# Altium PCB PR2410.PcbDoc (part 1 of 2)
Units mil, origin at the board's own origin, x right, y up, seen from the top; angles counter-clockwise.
Board outline 2750 x 3900 mil, 2 copper layers (Top Layer, Bottom Layer), stack 61.6 mil thick; 140 components, 78 nets, 324 pads, 132 vias.
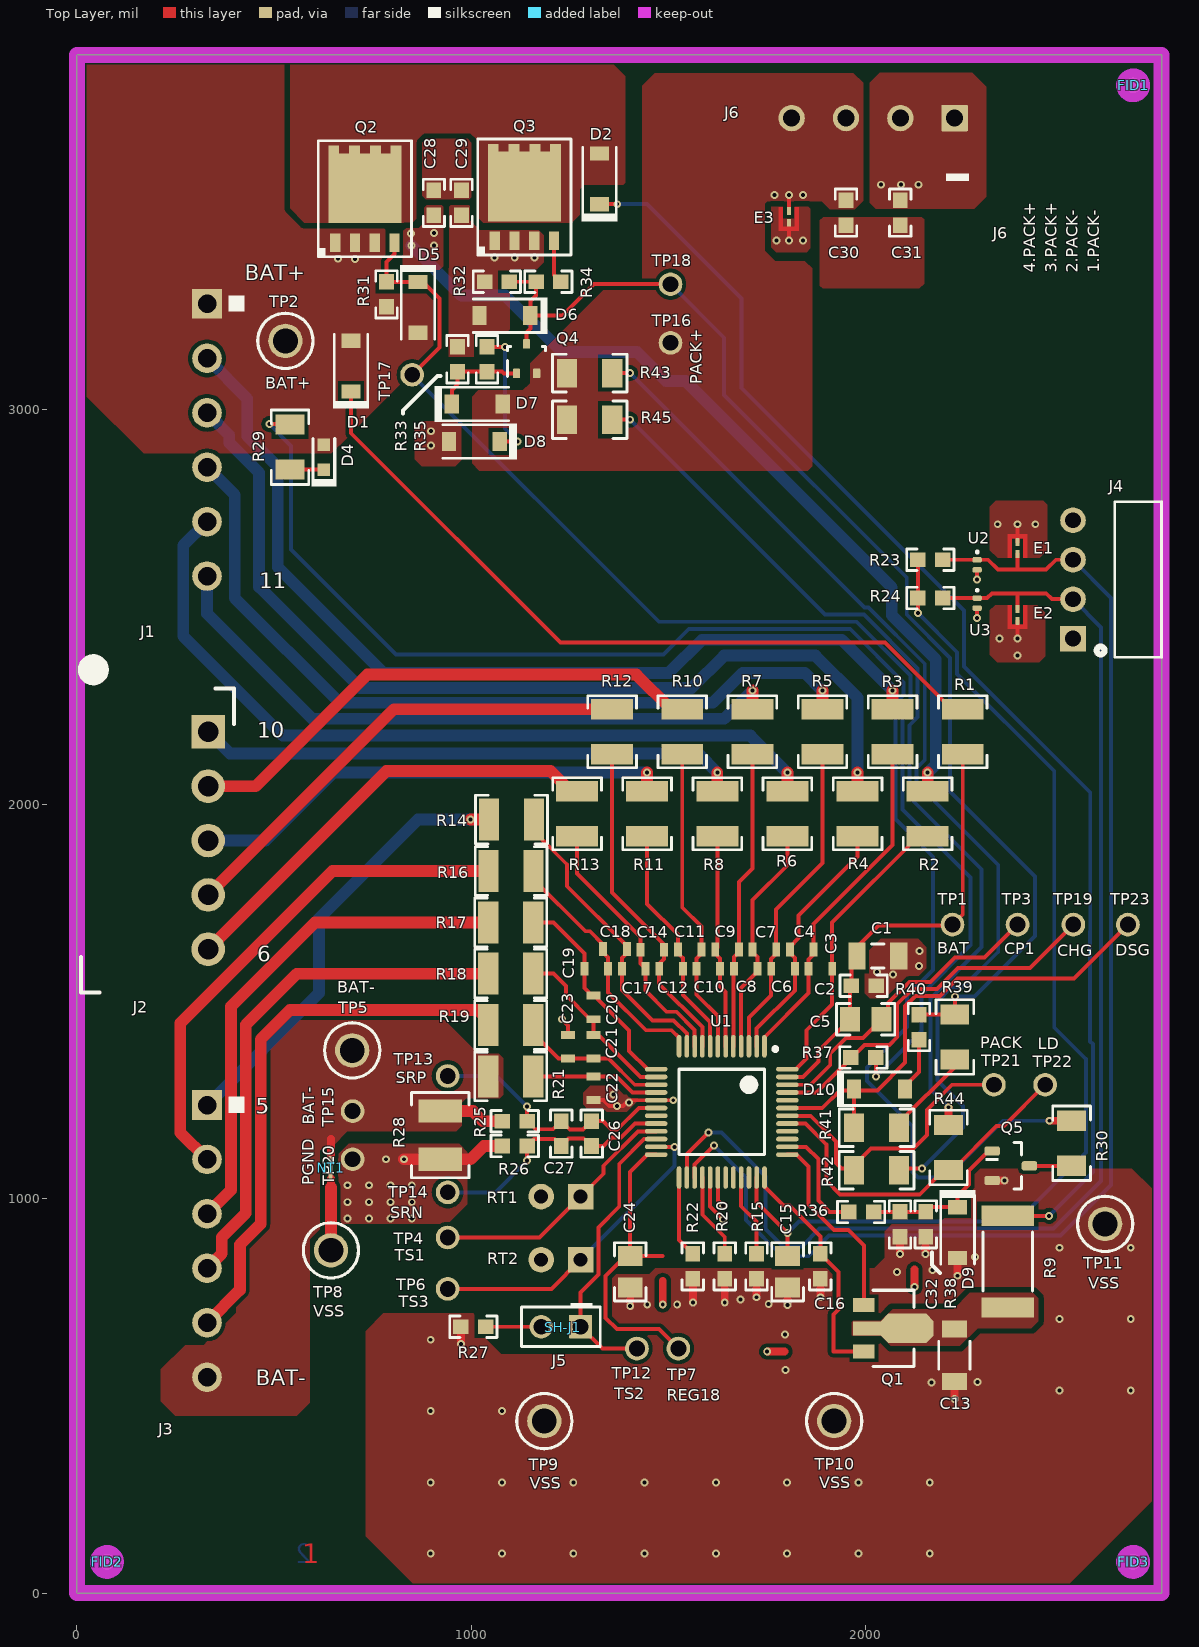
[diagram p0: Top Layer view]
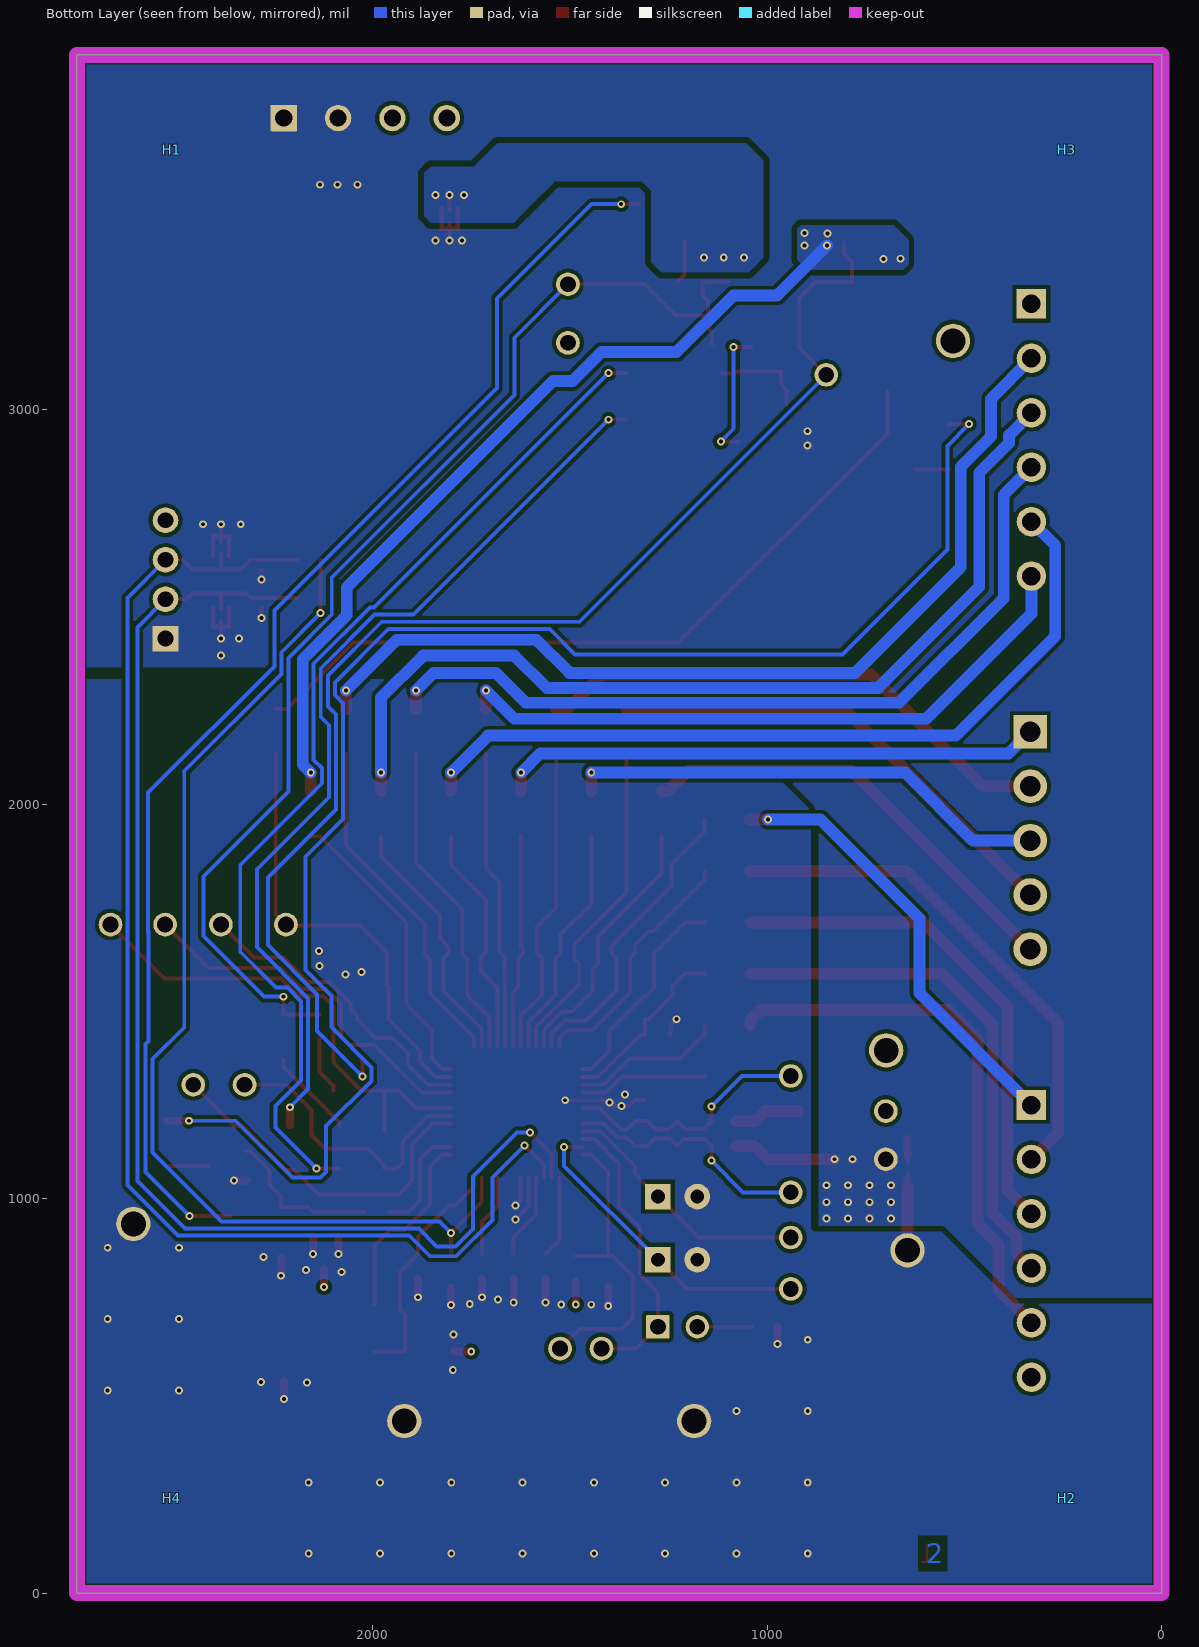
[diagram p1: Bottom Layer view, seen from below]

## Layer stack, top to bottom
Top Solder: solder mask 0.4, Solder Resist, Dk 3.5
Top Layer: signal copper 2.8
Dielectric: prepreg 56, FR-4 High Tg, Dk 4.2
Bottom Layer: signal copper 2.8
Bottom Solder: solder mask 0.4, Solder Resist, Dk 3.5

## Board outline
0,0 2750,0 2750,3900 0,3900

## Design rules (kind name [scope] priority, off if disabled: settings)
AcuteAngle [All] p1: minimum=4.50000000000000E+0001 checktracksonly=FALSE
AssemblyTestPointUsage [All] p1: valid=2
BoardOutlineClearance BoardOutlineClearance_MountingHoles [OnCopper and InComponentClass('Mounting Holes')] p1: gap=39.37 ignorepadtopadclearanceinfootprint=FALSE
BoardOutlineClearance BoardOutlineClearance_Poly [OnCopper and IsPoly] p2: gap=20 ignorepadtopadclearanceinfootprint=FALSE
BoardOutlineClearance [OnCopper and Not InComponentClass('Logo') and not InComponentClass('FiducialMark') and not InRegion(1000,500,4000,800) and not InPoly] p3: gap=18 ignorepadtopadclearanceinfootprint=FALSE
Clearance Clearance_FiducialMark [IsKeepOut and InComponentClass('FiducialMark') vs IsPad and InComponentClass('FiducialMark')] p1: gap=0 ignorepadtopadclearanceinfootprint=FALSE
Clearance Clearance_Iskeepot [IsKeepOut] p2: gap=5 ignorepadtopadclearanceinfootprint=FALSE
Clearance Clearance_NPTH [IsThruPin And (PadIsPlated = 'False')] p3: gap=20 ignorepadtopadclearanceinfootprint=FALSE
Clearance Clearance_Poly-poly [InPolygon vs InPolygon] p4: gap=15 ignorepadtopadclearanceinfootprint=FALSE
Clearance Clearance_Polygon [InPolygon] p5: gap=10 ignorepadtopadclearanceinfootprint=FALSE
Clearance [All] p6: gap=7.87 ignorepadtopadclearanceinfootprint=FALSE
ComponentClearance ComponentClearance_shunt [HasFootprint('CONN_PEC02SAAN') vs HasFootprint('SNT-100-BK-G')] p1: gap=0 collisioncheckmode=3 verticalgap=0 showdistances=FALSE
ComponentClearance ComponentClearance_Screw-Nut [(HasFootprint('Keystone_1902C')) vs (HasFootprint('NY PMS 440 0025 PH'))] p2: gap=5 collisioncheckmode=3 verticalgap=10 showdistances=FALSE
ComponentClearance [All] p3: gap=10 collisioncheckmode=3 verticalgap=10 showdistances=FALSE
DiffPairsRouting [All] p1: maxlimit=100 minlimit=10 mostfreqgap=10 toplayer_minwidth=15 toplayer_maxwidth=15 toplayer_prefwidth=15 bottomlayer_minwidth=15 bottomlayer_maxwidth=15 bottomlayer_prefwidth=15 maxuncoupledlength=1000
FabricationTestPointUsage TestPointUsage [All] p1: valid=2 allowmultiple=FALSE
FabricationTestpoint Testpoint [All] p1: side=3 testpointundercomponent=TRUE minsize=40 maxsize=100 preferedsize=60 minholesize=0 maxholesize=40 preferedholesize=32 testpointgrid=1 allowsidetop=TRUE allowsidebottom=TRUE usegrid=TRUE gridtolerance=0.01
FanoutControl Fanout_LCC [IsLCC] p1: bgadir=Out bgaviamode=Centered fanoutstyle=Auto fanoutdirection=Alternating viagrid=1 // Fanout_LCC (Default Rule)
FanoutControl Fanout_BGA [IsBGA] p2: bgadir=Out bgaviamode=Centered fanoutstyle=Auto fanoutdirection=Alternating viagrid=1 // Fanout_BGA (Default Rule)
FanoutControl Fanout_Default [All] p4: bgadir=Out bgaviamode=Centered fanoutstyle=Auto fanoutdirection=Alternating viagrid=1 // Fanout_Default (Default Rule)
FanoutControl Fanout_Small [(CompPinCount < 5)] p5: bgadir=Out bgaviamode=Centered fanoutstyle=Auto fanoutdirection=OutThenIn viagrid=1 // Fanout_Small (Default Rule)
HoleSize [All] p1: absolutevalues=TRUE maxlimit=251 minlimit=7.87 maxpercent=80.000 minpercent=20.000
HoleToHoleClearance [All] p1: gap=12 allowstackedmicrovias=TRUE
MinimumAnnularRing MinimumAnnularRing_ThermalPadVias [IsVia] p1: minimumring=5
MinimumAnnularRing [All] p2: minimumring=7.5
MinimumSolderMaskSliver MinimumSolderMaskSliver_Logo [InComponentClass('Logo') vs InComponentClass('Logo')] p1: minsoldermaskwidth=0.7
MinimumSolderMaskSliver [All] p2: minsoldermaskwidth=3.9
PlaneConnect [All] p1: planeconnectstyle=Relief reliefexpansion=10 reliefentries=4 reliefconductorwidth=10 reliefairgap=10
PolygonConnect [All] p1: connectstyle=Direct reliefconductorwidth=10 reliefentries=4 polygonreliefangle="90 Angle" airgapwidth=10
RoutingVias ThermalPadVias [IsVia and InAnyComponent] p1: holewidth=7.87 width=19.68 viastyle="Through Hole" minholewidth=7.87 minwidth=19.68 maxholewidth=12.99 maxwidth=23.62
RoutingVias [All] p2: holewidth=16 width=34 viastyle="Through Hole" minholewidth=7.87 minwidth=20 maxholewidth=40 maxwidth=65
SilkToBoardRegionClearance [Not ((IsComment or IsDesignator) And (Hide <> 'False')) and not InRegion(1000,500,4000,800)] p1:
SilkToSilkClearance SilkToSilkClearance_Pb-FreeLogo [(HasFootprint('Pb-Free_Overlay_Medium') OR HasFootprint('Pb-Free_Overlay_Small')) vs (HasFootprint('Pb-Free_Overlay_Medium') OR HasFootprint('Pb-Free_Overlay_Small'))] p1: silktosilkclearance=0
SilkToSilkClearance [All] p2: silktosilkclearance=4
SilkToSolderMaskClearance SilkToComponentPadClearance [(IsPad or IsFill or IsRegion) and InAnycomponent] p1: minsilkscreentomaskgap=5 clearancetoexposedcopper=TRUE
SilkToSolderMaskClearance "Silk to Solder Mask Opening" [All] p2: minsilkscreentomaskgap=3.94 clearancetoexposedcopper=FALSE
SolderMaskExpansion SolderMaskExpansion_NPTH [IsThruPin And (PadIsPlated = 'False')] p1: expansion=5
SolderMaskExpansion SolderMaskExpansion_PTH [IsThruPin] p2: expansion=2.5
SolderMaskExpansion [All] p3: expansion=0
UnRoutedNet [All] p1: checkbadconnections=TRUE
Width [All] p1: maxlimit=100 minlimit=6 preferedwidth=10 checkconnectedcopper=TRUE
13 further rules are at their usual default settings.

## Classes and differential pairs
component class Shunt: SH-J1
component class Header: J5
component class PR2410_Monitor: C1 C2 C3 C4 C5 C6 C7 C8 C9 C10 C11 C12 C13 C14 C15 C16 C17 C18 C19 C20 C21 C22 C23 C24 C26 C27 D1 D2 E1 E2 J1 J2 J3 J4 J5 NT1 Q1 R1 R2 R3 R4 R5 R6 R7 R8 R9 R10 R11 R12 R13 R14 R15 R16 R17 R18 R19 R20 R21 R22 R23 R24 R25 R26 R27 R28 RT1 RT2 TP1 TP2 TP3 TP4 TP5 TP6 TP7 TP8 TP9 TP10 TP11 TP12 TP13 TP14 TP15 U1 U2 U3
component class PR2410_FETs: C28 C29 C30 C31 C32 D4 D5 D6 D7 D8 D9 D10 E3 J6 Q2 Q3 Q4 Q5 R29 R30 R31 R32 R33 R34 R35 R36 R37 R38 R39 R40 R41 R42 R43 R44 R45 TP16 TP17 TP18 TP19 TP20 TP21 TP22 TP23
component class PR2410_Hardware: FID1 FID2 FID3 H1 H2 H3 H4 SH-J1 ZZ1 ZZ2 ZZ3 ZZ4
component class FiducialMark: FID1 FID2 FID3
component class AssemblyNote: ZZ1 ZZ2 ZZ3 ZZ4

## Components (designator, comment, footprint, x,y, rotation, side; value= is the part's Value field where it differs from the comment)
C1 "C3216X7R2A105K160AA" 1206_180L 2030.61,1615 r0 top value=1uF
C2 "GCM1885C2A101JA16D" 0603 1994.88,1540 r0 top value=100pF
C3 "C1608X7R1H224K080AB" 0603S 1885,1583.08 r180 top value=0.22uF
C4 "C1608X7R1H224K080AB" 0603S 1837.67,1632.08 r180 top value=0.22uF
C5 "GCM219R71E474KA55D" 0805_HV 1999.88,1455 r0 top value=0.47uF
C6 "C1608X7R1H224K080AB" 0603S 1790.33,1583.08 r180 top value=0.22uF
C7 "C1608X7R1H224K080AB" 0603S 1743,1632.08 r180 top value=0.22uF
C8 "C1608X7R1H224K080AB" 0603S 1695.67,1583.08 r180 top value=0.22uF
C9 "C1608X7R1H224K080AB" 0603S 1648.33,1632.08 r180 top value=0.22uF
C10 "C1608X7R1H224K080AB" 0603S 1601,1583.08 r180 top value=0.22uF
C11 "C1608X7R1H224K080AB" 0603S 1553.67,1632.08 r180 top value=0.22uF
C12 "C1608X7R1H224K080AB" 0603S 1506.33,1583.08 r180 top value=0.22uF
C13 "C3216X7R2A105K160AA" 1206_180 2225,603 r270 top value=1uF
C14 "C1608X7R1H224K080AB" 0603S 1459,1631.08 r180 top value=0.22uF
C15 "EMK212B7105KG-T" 0805_HV 1801.91,814.49 r90 top value=1uF
C16 "C0603C223K4RACTU" 0603 1885,828.5 r90 top value=0.022uF
C17 "C1608X7R1H224K080AB" 0603S 1411.67,1583.08 r180 top value=0.22uF
C18 "C1608X7R1H224K080AB" 0603S 1364.33,1633.08 r180 top value=0.22uF
C19 "C1608X7R1H224K080AB" 0603S 1317,1583.08 r180 top value=0.22uF
C20 "C1608X7R1H224K080AB" 0603S 1310,1485 r270 top value=0.22uF
C21 "C1608X7R1H224K080AB" 0603S 1310,1385 r270 top value=0.22uF
C22 "C1608X7R1H224K080AB" 0603S 1310,1280 r270 top value=0.22uF
C23 "C1608X7R1H224K080AB" 0603S 1245,1385 r90 top value=0.22uF
C24 "EMK212B7225KG-T" 0805_HV 1402.8,814.49 r90 top value=2.2uF
C26 "GCM1885C2A101JA16D" 0603 1305,1165 r270 top value=100pF
C27 "885012206095" 0603 1228,1165 r270 top value=0.1uF
C28 "GCJ188R72A104KA01D" 0603 905,3525 r270 top value=0.1uF
C29 "GCJ188R72A104KA01D" 0603 975,3525 r90 top value=0.1uF
C30 "GCJ188R72A104KA01D" 0603 1950,3500 r90 top value=0.1uF
C31 "GCJ188R72A104KA01D" 0603 2087.8,3500 r270 top value=0.1uF
C32 "885012206095" 0603 2087,934.72 r90 top value=0.1uF
D1 "BAT46W-7-F" SOD-123 695,3111 r90 top value=100V
D2 "BAT46W-7-F" SOD-123 1325,3586.02 r90 top value=100V
D4 "150060RS75000" WL-SMCW_RED 626,2880 r90 top value=Red
D5 "MMSZ5246B-7-F" SOD-123 865,3260 r270 top value=16V
D6 "MMSZ5246B-7-F" SOD-123 1085,3238.98 r180 top value=16V
D7 "MMSZ5246B-7-F" SOD-123 1015,3015 r0 top value=16V
D8 "1N4148W-7-F" SOD-123 1007.73,2920 r180 top value=100V
D9 "MMSZ4697T1G" SOD-123 2233,914 r270 top value=10V
D10 "BAT46W-7-F" SOD-123 2035,1278.57 r0 top value=100V
E1 "Spark Gap" SPARK_GAP2 2385,2655 r180 top
E2 "Spark Gap" SPARK_GAP2 2385,2475 r0 top
E3 "Spark Gap" SPARK_GAP2 1805,3484.45 r0 top
FID1 "Fiducial" Fiducial10-20 2678,3823 r0 top
FID2 "Fiducial" Fiducial10-20 76,79 r0 top
FID3 "Fiducial" Fiducial10-20 2678,79 r0 top
H1 "SJ-5303 (CLEAR)" Bumpon_SJ5003Transparent 2510,3660 r270 bottom
H2 "SJ-5303 (CLEAR)" Bumpon_SJ5003Transparent 240,240 r180 bottom
H3 "SJ-5303 (CLEAR)" Bumpon_SJ5003Transparent 240,3660 r0 bottom
H4 "SJ-5303 (CLEAR)" Bumpon_SJ5003Transparent 2510,240 r90 bottom
J1 "395021006" HEADER_395021006 329.81,2923.64 r270 top
J2 "395021005" HEADER_395021005 195.01,1908.03 r270 top
J3 "395021006" HEADER_395021006 329.81,892.43 r270 top
J4 "22/05/3041" CONN_22-05-3041 2750,2570 r90 top
J5 "PEC02SAAN" CONN_PEC02SAAN 1227,675.28 r180 top
J6 "OSTTE040161" FP-OSTTE040161_HDR4-MFG 2018.9,3743.94 r180 top
NT1 "Net-Tie" Net-Tie_10milWide_30milLong 643,1078 r90 top net-tie
Q1 "FCX495TA" SOT-89-3 2070,671.35 r0 top value="150 V"
Q2 "BSC160N15NS5ATMA1" PG-TDSON-8 730,3535.47 r90 top value=150V
Q3 "BSC160N15NS5ATMA1" PG-TDSON-8 1134.45,3539.76 r90 top value=150V
Q4 "MOSFET_N_D3G1S2" SOT-323 1140,3130 r90 top value=60V
Q5 "PMV213SN,215" SOT-23 2367.76,1083.35 r0 top value=100V
R1 "CRCW1210100RFKEA" 1210 2246,2184.09 r90 top value=100
R2 "ERJ-14YJ200U" 1210 2157.09,1976.09 r270 top value=20
R3 "ERJ-14YJ200U" 1210 2068.18,2184.09 r270 top value=20
R4 "ERJ-14YJ200U" 1210 1979.27,1976.09 r270 top value=20
R5 "ERJ-14YJ200U" 1210 1890.36,2184.09 r270 top value=20
R6 "ERJ-14YJ200U" 1210 1801.45,1976.09 r270 top value=20
R7 "ERJ-14YJ200U" 1210 1712.55,2184.09 r270 top value=20
R8 "ERJ-14YJ200U" 1210 1623.64,1976.09 r270 top value=20
R9 "CRCW2512300RJNEG" 2512 2360,840.35 r90 top value=300
R10 "ERJ-14YJ200U" 1210 1534.73,2184.09 r270 top value=20
R11 "ERJ-14YJ200U" 1210 1445.82,1976.09 r270 top value=20
R12 "ERJ-14YJ200U" 1210 1356.91,2184.09 r270 top value=20
R13 "ERJ-14YJ200U" 1210 1268,1976.09 r270 top value=20
R14 "ERJ-14YJ200U" 1210 1101.91,1961 r0 top value=20
R15 "CRCW06031K00JNEA" 0603 1723.36,828.5 r90 top value=1.0k
R16 "ERJ-14YJ200U" 1210 1100.91,1830.8 r0 top value=20
R17 "ERJ-14YJ200U" 1210 1100,1700.6 r0 top value=20
R18 "ERJ-14YJ200U" 1210 1100,1570.4 r0 top value=20
R19 "ERJ-14YJ200U" 1210 1100,1440.2 r0 top value=20
R20 "CRCW06031K00JNEA" 0603 1642.53,828.5 r90 top value=1.0k
R21 "ERJ-14YJ200U" 1210 1100,1310 r0 top value=20
R22 "CRCW06031K00JNEA" 0603 1561.71,828.5 r90 top value=1.0k
R23 "CRCW060310K0JNEA" 0603 2163.76,2620 r0 top value=10k
R24 "CRCW060310K0JNEA" 0603 2163.76,2522.8 r0 top value=10k
R25 "Resistor" 0603 1110,1196.5 r0 top value=100
R26 "Resistor" 0603 1110,1133.5 r0 top value=100
R27 "CRCW060310K0JNEA" 0603 1005,675.28 r0 top value=10k
R28 "Resistor" 1210M 921,1161 r90 top value=0.001
R29 "CRCW12067K50JNEA" 1206 540,2905.59 r270 top value=7.5k
R30 "CRCW12067K50JNEA" 1206 2522,1140.43 r90 top value=7.5k
R31 "Resistor" 0603 785,3292.97 r90 top value=10Meg
R32 "Resistor" 0603 1065,3325 r0 top value=10Meg
R33 "Resistor" 0603 965,3128.37 r270 top value=10Meg
R34 "CRCW06030000Z0EA" 0603 1195.53,3325 r180 top value=0
R35 "Resistor" 0603 1040,3128.37 r90 top value=10k
R36 "Resistor" 0603 1988.5,966.22 r180 top value=5.1k
R37 "CRCW06035K10JNEA" 0603 1994,1358 r0 top value=5.1k
R38 "Resistor" 0603 2151.96,934.72 r90 top value=20k
R39 "CRCW12065K10JNEA" 1206 2226.02,1410 r90 top value=5.1k
R40 "CRCW06037K50FKEA" 0603 2135,1435 r90 top value=7.50k
R41 "CRCW12065K10JNEA" 1206 2027.62,1179.7 r0 top value=5.1k
R42 "CRCW12065K10JNEA" 1206 2027.62,1072 r180 top value=5.1k
R43 "CRCW12065K10JNEA" 1206 1300,3093.27 r0 top value=5.1k
R44 "CRCW12065K10JNEA" 1206 2210,1129.76 r270 top value=5.1k
R45 "CRCW12065K10JNEA" 1206 1300,2975.16 r0 top value=5.1k
RT1 "Thermistor" THERMISTOR_103AT-2 1227,1005.28 r180 top value=10k
RT2 "Thermistor" THERMISTOR_103AT-2 1227,845.28 r180 top value=10k
SH-J1 "SNT-100-BK-G" SNT-100-BK-G 1231.39,674 r180 top value=1x2
TP1 "TESTPOINT" TP_VIA_060RND040 2220,1695 r0 top
TP2 "TESTPOINT" Keystone5010 528.47,3175 r0 top
TP3 "TESTPOINT" TP_VIA_060RND040 2385,1695 r0 top
TP4 "TESTPOINT" TP_VIA_060RND040 940,901.5 r0 top
TP5 "TESTPOINT" Keystone5011 698,1376 r0 top
TP6 "TESTPOINT" TP_VIA_060RND040 940,771.18 r0 top
TP7 "TESTPOINT" TP_VIA_060RND040 1525,620 r90 top
TP8 "5006" Keystone5006 644,869 r180 top
TP9 "5006" Keystone5006 1185,436 r180 top
TP10 "5006" Keystone5006 1920,436 r180 top
TP11 "5006" Keystone5006 2607,936 r180 top
TP12 "TESTPOINT" TP_VIA_060RND040 1420,620 r90 top
TP13 "TESTPOINT" TP_VIA_060RND040 940,1311 r270 top
TP14 "TESTPOINT" TP_VIA_060RND040 940,1016 r270 top
TP15 "TESTPOINT" TP_VIA_060RND040 699,1222.02 r90 top
TP16 "TESTPOINT" TP_VIA_060RND040 1505,3170 r90 top
TP17 "TESTPOINT" TP_VIA_060RND040 850,3089 r90 top
TP18 "TESTPOINT" TP_VIA_060RND040 1505,3318.7 r90 top
TP19 "TESTPOINT" TP_VIA_060RND040 2526.5,1695 r90 top
TP20 "TESTPOINT" TP_VIA_060RND040 699,1099.98 r180 top
TP21 "TESTPOINT" TP_VIA_060RND040 2325,1288.9 r180 top
TP22 "TESTPOINT" TP_VIA_060RND040 2455,1288.9 r90 top
TP23 "TESTPOINT" TP_VIA_060RND040 2664.95,1695 r90 top
U1 "bq76952PFBR" PFB0048A_N 1635,1220 r270 top locked
U2 "TPD1E10B06DPYR" DPY0002A 2282.52,2607.21 r270 top
U3 "TPD1E10B06DPYR" DPY0002A 2282.52,2510 r270 top
ZZ1 "These assemblies are ESD sensitive, ESD precautions shall be observed." AssemblyNote -638,4601 r0 top
ZZ2 "These assemblies must be clean and free from flux and all contaminants. Use of no clean flux is not acceptable." AssemblyNote -638,4501 r0 top
ZZ3 "These assemblies must comply with workmanship standards IPC-A-610 Class 2, unless otherwise specified." AssemblyNote -638,4401 r0 top
ZZ4 "Indication provided for the D* components at their cathode side." AssemblyNote -636,4300 r0 top

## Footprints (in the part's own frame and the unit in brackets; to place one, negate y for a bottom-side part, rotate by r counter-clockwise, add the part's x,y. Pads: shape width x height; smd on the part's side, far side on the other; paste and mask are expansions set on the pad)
0603 [mm] "0603 from SM-752 data"
  rect 1x0.95 smd: 1(-0.8,0) 2(0.8,0)
  silkscreen extent -1.52,-0.69 1.52,0.69, body extent -0.87,-0.47 0.87,0.47, height 1
0603S [mil]
  rect 20x35 smd: 1(-30,0) 2(30,0)
  body extent -34,-19 34,19, height 39
0805_HV [mil] "0805 with 30mil clearance between pads"
  rect 50x63 smd: 1(-40,0) 2(40,0)
  silkscreen extent -74,-40 74,40, body extent -43,-29 43,29, height 57
1206 [mm] "1206 from SM-752 data"
  rect 1.3x1.85 smd: 1(-1.45,0) 2(1.45,0)
  silkscreen extent -2.4,-1.21 2.4,1.21, body extent -1.7,-0.9 1.7,0.9, height 1.35
1206_180 [mm] "1206_180"
  rect 1.1x1.6 smd: 1(-1.7,0) 2(1.7,0)
  silkscreen extent -0.9,-1 0.9,1, body extent -1.75,-0.95 1.75,0.95, height 1.8
1206_180L [mm] "1206_180"
  rect 1.1x1.75 smd: 1(-1.35,0) 2(1.35,0)
  silkscreen extent -0.4,-0.77 0.4,0.77, body extent -1.75,-0.95 1.75,0.95, height 1.8
1210 [mm] "1210 from SM-752 data"
  rect 1.3x2.7 smd: 1(-1.45,0) 2(1.45,0)
  silkscreen extent -2.32,-1.57 2.32,1.57, body extent -1.7,-1.35 1.7,1.35, height 1.35
1210M [mm] "1210 from SM-752 data"
  rect 1.5x2.8 smd: 1(-1.55,0) 2(1.55,0)
  silkscreen extent -2.75,-1.85 2.75,1.85, body extent -1.7,-1.35 1.7,1.35, height 1.35
2512 [mm] "Chip Resistor, Body 6.3x3.2mm, IPC Medium Density"
  rect 1.3x3.4 smd: 1(-2.95,0) 2(2.95,0)
  silkscreen extent -1.9,-1.6 1.9,1.6, body extent -3.22,-1.67 3.22,1.67, height 0.71
AssemblyNote [mil] "Assembly Note"
Bumpon_SJ5003Transparent [mil] "3M Hemispherical Bumpon transparent"
  round 1 on Mech4: 0(0,0)
  body extent -219,-219 219,219, height 197
CONN_22-05-3041 [mm] "MOLEX"
  rect 1.65x1.65 hole 1.02: 1(-3.81,5.7)
  round 1.65 hole 1.02: 2(-1.27,5.7) 3(1.27,5.7) 4(3.81,5.7)
  silkscreen extent -5,0 5,4.18, body extent -5,-6.91 5,6.02, height 6.37
CONN_PEC02SAAN [mm] "SULLINS"
  rrect7% 1.5x1.5 hole 1.016: 1(-1.27,0)
  round 1.5 hole 1.016: 2(1.27,0)
  silkscreen extent -2.54,-1.52 2.54,1.27, body extent -2.54,-1.27 2.54,1.27, height 8.38
DPY0002A [mm] "X1SON-2"
  rrect57% 0.35x0.6 smd paste-0.5 mask-0.05: 1(-0.325,0) 2(0.325,0)
  rrect33% 0.3x0.5 on Top Paste: 1S(-0.35,0) 2S(0.35,0)
  silkscreen extent -0.85,-0.02 -0.8,0.03, body extent -0.5,-0.3 0.5,0.3, height 0.45
Fiducial10-20 [mm]
  round 1 smd mask+0.5: 1(0,0)
  Top Layer keep-out circle w1.178: c0,0 r0.5
FP-OSTTE040161_HDR4-MFG [mm]
  rrect6% 1.7x1.7 hole 1.1 paste-1000: 1(-5.25,0.1)
  round 1.7 hole 1.1 paste-1000: 2(-1.75,0.1) 3(1.75,0.1) 4(5.25,0.1)
  body extent -7.68,-3.75 7.68,3.75, height 0.25
HEADER_395021005 [mil] "MOLEX"
  rect 85x85 hole 52: 1(-275.59,137.8)
  round 85 hole 52: 2(-137.8,137.8) 3(0,137.8) 4(137.8,137.8) 5(275.59,137.8)
  silkscreen extent -453,-184 386,203, body extent -371,-172 373,188, height 277
HEADER_395021006 [mil] "Molex"
  rect 75x75 hole 47: 1(-345,0)
  round 75 hole 47: 2(-207,0) 3(-69,0) 4(69,0) 5(207,0) 6(345,0)
  silkscreen extent -366,55 -326,95, body extent -441,-310 441,50, height 270
Keystone5006 [mil] "Keystone Compact loops"
  round 87 hole 63: 1(0,0)
  silkscreen extent -70,-70 70,70, body extent -63,-63 62,63, height 225
Keystone5010 [mil] "Keystone Multipurpose loops"
  round 87 hole 63: 1(0,0)
  silkscreen extent -70,-70 70,70, body extent -63,-63 63,62, height 319
Keystone5011 [mil] "Keystone Multipurpose loops"
  round 87 hole 63: 1(0,0)
  silkscreen extent -70,-70 70,70, body extent -63,-63 63,62, height 319
Net-Tie_10milWide_30milLong [mil] "10mil net tie, no solder mask opening, no solder paste"
  rect 30x10 smd paste-5 mask-5: 1(-15,0) 2(15,0)
PFB0048A_N [mm] "Thin QFP, 48-Leads, Body 7x7mm, Pitch 0.5mm, IPC Medium Density"
  oval 1.45x0.3 smd: 1(-4.225,2.75) 2(-4.225,2.25) 3(-4.225,1.75) 4(-4.225,1.25) 5(-4.225,0.75) 6(-4.225,0.25) 7(-4.225,-0.25) 8(-4.225,-0.75) 9(-4.225,-1.25) 10(-4.225,-1.75) 11(-4.225,-2.25) 12(-4.225,-2.75) 25(4.225,-2.75) 26(4.225,-2.25) 27(4.225,-1.75) 28(4.225,-1.25) 29(4.225,-0.75) 30(4.225,-0.25) 31(4.225,0.25) 32(4.225,0.75) 33(4.225,1.25) 34(4.225,1.75) 35(4.225,2.25) 36(4.225,2.75)
  oval 0.3x1.45 smd: 13(-2.75,-4.225) 14(-2.25,-4.225) 15(-1.75,-4.225) 16(-1.25,-4.225) 17(-0.75,-4.225) 18(-0.25,-4.225) 19(0.25,-4.225) 20(0.75,-4.225) 21(1.25,-4.225) 22(1.75,-4.225) 23(2.25,-4.225) 24(2.75,-4.225) 37(2.75,4.225) 38(2.25,4.225) 39(1.75,4.225) 40(1.25,4.225) 41(0.75,4.225) 42(0.25,4.225) 43(-0.25,4.225) 44(-0.75,4.225) 45(-1.25,4.225) 46(-1.75,4.225) 47(-2.25,4.225) 48(-2.75,4.225)
  silkscreen extent -4.17,-2.75 2.75,3.58, body extent -4.5,-4.5 4.5,4.5, height 1.07
PG-TDSON-8 [mm] "Infineon recommended land pattern"
  rect 1.2x0.65 smd: 1(-2.825,1.905) 2(-2.825,0.635) 3(-2.825,-0.635) 4(-2.825,-1.905)
  rect 0.5x0.7 smd: 5(3.175,-2) 6(3.175,-0.675) 7(3.175,0.675) 8(3.175,2)
  rect 4.5x4.7 smd paste-2.25: 9(0.675,0)
  silkscreen extent -3.74,-3 3.74,3, body extent -3.17,-2.89 3.17,2.9, height 1.1
SNT-100-BK-G [mil] "Samtec STEP model"
  round 1 on Mech3: 0(0,0)
  body extent -100,-50 100,50, height 344
SOD-123 [mm] "On Semi recommended land pattern"
  rect 0.915x1.22 smd: 1(-1.637,0) 2(1.637,0)
  silkscreen extent -2.74,-1.17 2.03,1.17, body extent -1.93,-0.9 1.93,0.9, height 1.35
SOT-23 [mm] "SOT23, 3-Leads, Body 2.9x1.3mm, Pitch 0.95mm, Lead Span 2.5mm, IPC Medium Density"
  rrect50% 1x0.6 smd: 1(-1.2,0.95) 2(-1.2,-0.95) 3(1.2,0)
  silkscreen extent -1.62,-1.5 0.7,1.5, body extent -1.16,-1.45 1.21,1.45, height 1
SOT-89-3 [mm] "SOT, 3-Leads, Body 4.6 x 2.6 mm, Pitch 1.5mm"
  rect 1.4x0.9 smd: 1(-1.9,1.5) 3(-1.9,-1.5)
  rect 1.8x0.9 smd: 2(-1.7,0)
  oct 3.4x1.9 smd: 4(0.9,0)
  silkscreen extent -1.3,-2.45 1.33,2.45, body extent -2.42,-2.28 1.83,2.32, height 1.62
SOT-323 [mm] "Diodes Inc recommended land pattern.  2016-02-24"
  rrect21% 0.6x0.47 smd: 1(-0.95,0.65) 2(-0.95,-0.65) 3(0.95,0)
  silkscreen extent -1.14,-1.22 0.77,1.22, body extent -1.13,-1.13 1.12,1.12, height 1.13
SPARK_GAP2 [mil] "Copied from PADS legacy libraries."
  rect 10x20 smd paste-20: 1(0,20) 2(0,-10)
  Top Layer region: -15,30 -25,30 -25,-30 25,-30 25,30 15,30 15,-20 -15,-20 -15,30
THERMISTOR_103AT-2 [mil] "SEMITEC"
  rect 65x65 hole 35: 1(-50,0)
  round 65 hole 35: 2(50,0)
  body extent -78,-47 79,47, height 338
TP_VIA_060RND040 [mil] "TP_VIA_060RND040"
  round 60 hole 40: 1(0,0)
WL-SMCW_RED [mm] "WURTH"
  rect 0.8x0.8 smd: 1(-0.8,0) 2(0.8,0)
  silkscreen extent -1.9,-0.8 1.2,0.8, body extent -0.85,-0.45 0.85,0.45, height 0.8

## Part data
C1 C13: library part CMP-0008710-2, "CAP, CERM, 1 uF, 100 V, +/- 10%, X7R, 1206", Cap_Case=1206_180, Manufacturer=TDK, Supplier Part Number 1=445-4467-1-ND, TempCo=X7R, Tolerance_%=10%, Value1="0.004575 ohm", Value2=100V, ValueDisplayed=1uF
C2 C26: library part CMP-0007130-4, "CAP, CERM, 100 pF, 100 V, +/- 5%, C0G/NP0, AEC-Q200 Grade 1, 0603", Cap_Case=0603, Manufacturer=MuRata, Supplier Part Number 1=490-4771-1-ND, TempCo=C0G/NP0, Tolerance_%=5%, Value1=Unknown, Value2=100V, ValueDisplayed=100pF
C3 C4 C6 C7 C8 C9 C10 C11 C12 C14 C17 C18 C19 C20 C21 C22 C23: library part CMP-0007047-4, "CAP, CERM, 0.22 uF, 50 V, +/- 10%, X7R, 0603", Cap_Case=0603, Manufacturer=TDK, Supplier Part Number 1=445-7408-1-ND, TempCo=X7R, Tolerance_%=10%, Value1="0.021699 ohm", Value2=50V, ValueDisplayed=0.22uF
C5: library part CMP-0008010-2, "CAP, CERM, 0.47 uF, 25 V, +/- 10%, X7R, AEC-Q200 Grade 1, 0805", Cap_Case=0805, Manufacturer=MuRata, Supplier Part Number 1=490-8044-1-ND, TempCo=X7R, Tolerance_%=10%, Value1=Unknown, Value2=25V, ValueDisplayed=0.47uF
C15: library part CMP-0008000-2, "CAP, CERM, 1 uF, 16 V, +/- 10%, X7R, 0805", Cap_Case=0805, Manufacturer="Taiyo Yuden", Supplier Part Number 1=587-1283-1-ND, TempCo=X7R, Tolerance_%=10%, Value1=Unknown, Value2=16V, ValueDisplayed=1uF
C16: library part CMP-0006900-4, "CAP, CERM, 0.022 uF, 16 V, +/- 10%, X7R, 0603", Cap_Case=0603, Manufacturer=Kemet, Supplier Part Number 1=399-1093-1-ND, TempCo=X7R, Tolerance_%=10%, Value1=Unknown, Value2=16V, ValueDisplayed=0.022uF
C24: library part CMP-0008001-2, "CAP, CERM, 2.2 uF, 16 V, +/- 10%, X7R, 0805", Cap_Case=0805, Manufacturer="Taiyo Yuden", Supplier Part Number 1=587-1431-1-ND, TempCo=X7R, Tolerance_%=10%, Value1=Unknown, Value2=16V, ValueDisplayed=2.2uF
C27 C32: library part CMP-0006837-4, "CAP, CERM, 0.1 uF, 50 V, +/- 10%, X7R, 0603", Cap_Case=0603, Manufacturer="Wurth Elektronik", TempCo=X7R, Tolerance_%=10%, Value1=Unknown, Value2=50V, ValueDisplayed=0.1uF
C28 C29 C30 C31: library part CMP-0064935-4, "CAP, CERM, 0.1 uF, 100 V,+/- 10%, X7R, AEC-Q200 Grade 1, 0603", Cap_Case=0603, Manufacturer=MuRata, Supplier Part Number 1=490-13420-1-ND, TempCo=X7R, Tolerance_%=10%, Value1=Unknown, Value2=100V, ValueDisplayed=0.1uF
D1 D2 D10: library part CMP-0028450-2, "Diode, Schottky, 100 V, 0.15 A, SOD-123", Manufacturer="Diodes Inc.", Value1=0.15A, Value2=0.6V
D4: library part CMP-0002947-3, "LED, Red, SMD", Color=Red, Manufacturer="Wurth Elektronik", Power_TotalModule=72mW, Value1=0.072W, Value2=2V
D5 D6 D7: library part CMP-0005754-4, "Diode, Zener, 16 V, 500 mW, SOD-123", Manufacturer="Diodes Inc.", Power_W=500mW, Value1=0.5W
D8: library part CMP-0029001-2, "Diode, Ultrafast, 100 V, 0.15 A, SOD-123", Manufacturer="Diodes Inc.", Value1=0.15A, Value2=1.25V
D9: library part CMP-0005740-3, "Diode, Zener, 10 V, 500 mW, SOD-123", Manufacturer="ON Semiconductor", Power_W=500mW, Value1=0.5W
E1 E2 E3: library part CMP-0079939-1
FID1 FID2 FID3: library part CMP-0077181-1, "Fiducial mark.  There is nothing to buy or mount.", Manufacturer=N/A
H1 H2 H3 H4: library part CMP-0003620-1, "Bumpon, Hemisphere, 0.44 X 0.20, Clear", Manufacturer=3M, Supplier Part Number 1=SJ5303-7-ND
J1 J3: library part CMP-0055336-1, "Terminal Block Header, 3.5mm 6x1, Tin, R/A, TH", Manufacturer=Molex, Supplier Part Number 1=WM7774-ND
J2: library part CMP-0055189-1, "Header (shrouded), 3.5mm, 5x1, R/A, TH", Manufacturer=Molex, Supplier Part Number 1=WM7773-ND
J4: library part CMP-0055187-1, "Header (friction lock), 100mil, 4x1, R/A, TH", Manufacturer=Molex, PartNumber=0022053041, Supplier Part Number 1=WM4302-ND
J5: library part CMP-0002337-1, "Header, 100mil, 2x1, Tin, TH", Color=Black, Current_A=3A, Manufacturer="Sullins Connector Solutions", Supplier Part Number 1=S1012E-02-ND, Voltage_V=1.8kV
J6: library part CMP-0087048-1, "TERM BLOCK 3.5MM VERT 4POS PCB", Current_A=10A, Manufacturer="On Shore Technology", Voltage_V=300V
NT1: library part CMP-0078142-3, "Single point connection between nets.", Manufacturer=N/A
Q1: library part CMP-0000510-2, "Transistor, NPN, 150 V, 1 A, AEC-Q101, SOT-89", Manufacturer="Diodes Inc.", Supplier Part Number 1=FCX495CT-ND, Value1="1 A", Value2=300
Q2 Q3: library part CMP-0067566-1, "MOSFET, N-CH, 150 V, 56 A, PG-TDSON-8", Alternate Manufacturer=None, Manufacturer="Infineon Technologies", Supplier Part Number 1=BSC160N15NS5ATMA1-ND, Value1="? ohm", Value2="19 nC"
Q4: library part CMP-0000774-1, "MOSFET, N-CH, 60 V, 0.31 A, SOT-323", Alternate Manufacturer=None, Manufacturer="Fairchild Semiconductor", PartNumber=2N7002KW, Supplier Part Number 1=2N7002KWCT-ND, Value1=1
Q5: library part CMP-0001015-3, "MOSFET, N-CH, 100 V, 1.9 A, SOT-23", Alternate Manufacturer=None, Manufacturer=Nexperia, Supplier Part Number 1=568-8112-1-ND, Value2="7 nC"
R1: library part CMP-0082536-1, "RES, 100, 1%, 0.5 W, AEC-Q200 Grade 0, 1210", Manufacturer=Vishay-Dale, Power_W=500mW, Supplier Part Number 1=541-100AACT-ND, TempCo="100 ppm/C", Tolerance_%=1%, Value2=0.5W, Value_Code=100R, ValueDisplayed=100
R2 R3 R4 R5 R6 R7 R8 R10 R11 R12 R13 R14 R16 R17 R18 R19 R21: library part CMP-0015332-2, "RES, 20, 5%, 0.5 W, 1210", Manufacturer=Panasonic, Power_W=500mW, Supplier Part Number 1=P20VCT-ND, TempCo="200 ppm/C", Tolerance_%=5%, Value2=0.5W, Value_Code=20R0, ValueDisplayed=20
R9: library part CMP-0015938-3, "RES, 300, 5%, 1 W, AEC-Q200 Grade 0, 2512", Manufacturer=Vishay-Dale, Power_W=1W, Supplier Part Number 1=541-300XCT-ND, TempCo="200 ppm/C", Tolerance_%=5%, Value_Code=300R, ValueDisplayed=300
R15 R20 R22: library part CMP-0025729-4, "RES, 1.0 k, 5%, 0.1 W, AEC-Q200 Grade 0, 0603", Manufacturer=Vishay-Dale, Power_W=100mW, Supplier Part Number 1=541-1.0KGCT-ND, TempCo="200 ppm/C", Tolerance_%=5%, Value2=0.1W, Value_Code=1k00, ValueDisplayed=1.0k
R23 R24 R27: library part CMP-0025701-4, "RES, 10 k, 5%, 0.1 W, AEC-Q200 Grade 0, 0603", Manufacturer=Vishay-Dale, Power_W=100mW, Supplier Part Number 1=541-10KGCT-ND, TempCo="200 ppm/C", Tolerance_%=5%, Value2=0.1W, Value_Code=10k0, ValueDisplayed=10k
R25 R26: library part CMP-0025700-4, "RES, 100, 5%, 0.1 W, AEC-Q200 Grade 0, 0603", Manufacturer=Vishay-Dale, PartNumber=CRCW0603100RJNEA, Power_W=100mW, Supplier Part Number 1=541-100GCT-ND, TempCo="200 ppm/C", Tolerance_%=5%, Value2=0.1W, Value_Code=100R, ValueDisplayed=100
R28: library part CMP-0015200-2, "RES, 0.001, 1%, 1 W, 1210", Manufacturer=Rohm, PartNumber=PMR25HZPFV1L00, Power_W=1W, Supplier Part Number 1=RHM.001APCT-ND, TempCo="100 ppm/C", Tolerance_%=1%, Value_Code=1L000, ValueDisplayed=0.001
R29 R30: library part CMP-0018728-3, "RES, 7.5 k, 5%, 0.25 W, AEC-Q200 Grade 0, 1206", Manufacturer=Vishay-Dale, Power_W=250mW, Supplier Part Number 1=541-7.5KECT-ND, TempCo="200 ppm/C", Tolerance_%=5%, Value2=0.25W, Value_Code=7k50, ValueDisplayed=7.5k
R31 R32 R33: library part CMP-0025702-4, "RES, 10 M, 5%, 0.1 W, AEC-Q200 Grade 0, 0603", Manufacturer=Vishay-Dale, PartNumber=CRCW060310M0JNEA, Power_W=100mW, Supplier Part Number 1=541-10MGCT-ND, TempCo="200 ppm/C", Tolerance_%=5%, Value2=0.1W, Value_Code=10M0, ValueDisplayed=10M
R34: library part CMP-0025697-4, "RES, 0, 5%, 0.1 W, AEC-Q200 Grade 0, 0603", Manufacturer=Vishay-Dale, Power_W=100mW, Supplier Part Number 1=541-0.0GCT-ND, TempCo="200 ppm/C", Tolerance_%=5%, Value2=0.1W, Value_Code=0000, ValueDisplayed=0
R35: library part CMP-0025701-4, "RES, 10 k, 5%, 0.1 W, AEC-Q200 Grade 0, 0603", Manufacturer=Vishay-Dale, PartNumber=CRCW060310K0JNEA, Power_W=100mW, Supplier Part Number 1=541-10KGCT-ND, TempCo="200 ppm/C", Tolerance_%=5%, Value2=0.1W, Value_Code=10k0, ValueDisplayed=10k
R36: library part CMP-0025830-4, "RES, 5.1 k, 5%, 0.1 W, AEC-Q200 Grade 0, 0603", Manufacturer=Vishay-Dale, PartNumber=CRCW06035K10JNEA, Power_W=100mW, Supplier Part Number 1=541-5.1KGCT-ND, TempCo="200 ppm/C", Tolerance_%=5%, Value2=0.1W, Value_Code=5k10, ValueDisplayed=5.1k
R37: library part CMP-0025830-4, "RES, 5.1 k, 5%, 0.1 W, AEC-Q200 Grade 0, 0603", Manufacturer=Vishay-Dale, Power_W=100mW, Supplier Part Number 1=541-5.1KGCT-ND, TempCo="200 ppm/C", Tolerance_%=5%, Value2=0.1W, Value_Code=5k10, ValueDisplayed=5.1k
R38: library part CMP-0025753-4, "RES, 20 k, 5%, 0.1 W, AEC-Q200 Grade 0, 0603", Manufacturer=Vishay-Dale, PartNumber=CRCW060320K0JNEA, Power_W=100mW, Supplier Part Number 1=541-20KGCT-ND, TempCo="200 ppm/C", Tolerance_%=5%, Value2=0.1W, Value_Code=20k0, ValueDisplayed=20k
R39 R41 R42 R43 R44 R45: library part CMP-0018703-3, "RES, 5.1 k, 5%, 0.25 W, AEC-Q200 Grade 0, 1206", Manufacturer=Vishay-Dale, Power_W=250mW, Supplier Part Number 1=541-5.1KECT-ND, TempCo="200 ppm/C", Tolerance_%=5%, Value2=0.25W, Value_Code=5k10, ValueDisplayed=5.1k
R40: library part CMP-0022601-4, "RES, 7.50 k, 1%, 0.1 W, AEC-Q200 Grade 0, 0603", Manufacturer=Vishay-Dale, Power_W=100mW, Supplier Part Number 1=541-7.50KHCT-ND, TempCo="100 ppm/C", Tolerance_%=1%, Value2=0.1W, Value_Code=7k50, ValueDisplayed=7.50k
RT1 RT2: library part CMP-0002341-2, "Thermistor NTC, 10.0k ohm, 1%, Disc, 5x8.4 mm", Manufacturer="SEMITEC Corporation", PartNumber=103AT-2, Power_W=10mW, Supplier Part Number 1=954-103AT-2, Tolerance_%=1%
SH-J1: library part CMP-0003623-3, "Shunt, 100mil, Gold plated, Black", Alternate Manufacturer=3M, Alternate PartNumber=969102-0000-DA, Manufacturer=Samtec, Supplier Part Number 1=SAM8858-ND
TP1 TP3 TP4 TP6 TP7 TP12 TP13 TP14 TP15 TP16 TP17 TP18 TP19 TP20 TP21 TP22 TP23: library part CMP-0078143-3, "TEST POINT.  No entry in BOM.", Manufacturer=N/A
TP2: library part CMP-0055147-1, "Test Point, Multipurpose, Red, TH", Color=Red, Manufacturer=Keystone, PartNumber=5010, Supplier Part Number 1=36-5010-ND
TP5: library part CMP-0055148-1, "Test Point, Multipurpose, Black, TH", Color=Black, Manufacturer=Keystone, PartNumber=5011, Supplier Part Number 1=36-5011-ND
TP8 TP9 TP10 TP11: library part CMP-0055143-1, "Test Point, Compact, Black, TH", Color=Black, Manufacturer=Keystone, Supplier Part Number 1=36-5006-ND
U1: library part CMP-0084230-1, "Multicell Battery Monitor and Protection Family, PFB0048A (TQFP-48)", Alternate Manufacturer="Texas Instruments", Alternate PartNumber=bq76952PFBT
U2 U3: library part CMP-0043093-4, "Single-Channel ESD in 0402 Package With 10pF Capacitance and 6V Breakdown, DPY0002A (X1SON-2)", Alternate Manufacturer="Texas Instruments", Alternate PartNumber=TPD1E10B06DPYT, Breakdown Voltage(Min)(V)=6, IO Capacitance(Typ)(pF)=10, Operating Temperature Range="-40 to 125 C", Rating=Catalog
ZZ1: library part CMP-0077236-1
ZZ2: library part CMP-0077237-1
ZZ3: library part CMP-0077238-1
ZZ4: library part CMP-0077238-1, "These assemblies must comply with workmanship standards IPC-A-610 Class 2, unless otherwise specified."

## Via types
v1: diameter 20, hole 10, Top Layer to Bottom Layer, tented top, 132 vias

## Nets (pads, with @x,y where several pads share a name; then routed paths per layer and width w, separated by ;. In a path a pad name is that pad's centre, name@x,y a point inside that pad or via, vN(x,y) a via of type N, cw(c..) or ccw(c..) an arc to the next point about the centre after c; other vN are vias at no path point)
1P: J3.5 R19.1 | length 1419.3
  Top Layer w30: J3.5@309.81,685.43 J3.5@319.81,695.43 ; J3.5@329.81,685.43 413,768.62 413,883 465.93,935.93 465.93,1403.93 540,1478 1017,1478 1042.91,1452.09 R19.1@1042.91,1440.2
2P: J3.4 R18.1 | length 1340.9
  Top Layer w30: J3.4@309.81,823.43 J3.4@319.81,833.43 ; J3.4@329.81,823.43 367,860.62 367,902 428.06,963.06 428.06,1441.06 557.4,1570.4 R18.1@1042.91,1570.4
3P: J3.3 R17.1 | length 1306
  Top Layer w30: J3.3@309.81,961.43 J3.3@319.81,971.43 ; J3.3@329.81,961.43 390.18,1021.8 390.18,1487.18 603.6,1700.6 R17.1@1042.91,1700.6
4P: J3.2 R16.1 | length 1315.3
  Top Layer w30: J3.2@329.81,1099.43 262,1167.24 262,1445 647.8,1830.8 R16.1@1043.83,1830.8
5P: J3.1 R14.1 | length 1125.7
  Top Layer w30: v1(997.83,1961) R14.1@1044.83,1961
  Bottom Layer w30: J3.1@329.81,1237.43 614,1521.62 614,1711 864,1961 v1(997.83,1961)
6P: J2.5 R13.1 | length 1157.4
  Top Layer w30: J2.5@312.81,1632.44 J2.5@322.81,1642.44 ; J2.5@332.81,1632.44 784.37,2084 1201,2084 1251.83,2033.17 R13.1@1268,2033.17
7P: J2.4 R12.1 | length 1233.3
  Top Layer w30: J2.4@312.81,1770.24 J2.4@322.81,1780.24 ; J2.4@332.81,1770.24 803.75,2241.17 R12.1@1356.91,2241.17
8P: J2.3 R11.1 | length 1231.3
  Top Layer w30: R11.1@1445.82,2033.17 v1(1445.82,2080.17)
  Bottom Layer w30: J2.3@332.81,1908.03 478.03,1908.03 650.17,2080.17 v1(1445.82,2080.17)
9P: J2.2 R10.1 | length 1355.6
  Top Layer w30: J2.2@332.81,2045.83 452.83,2045.83 736,2329 1418.71,2329 1506.54,2241.17 R10.1@1534.73,2241.17
10P: J2.1 R8.1 | length 1380.7
  Top Layer w30: R8.1@1623.64,2033.17 v1(1623.64,2080.17)
  Bottom Layer w30: J2.1@332.81,2183.62 387.43,2129 1574.81,2129 v1(1623.64,2080.17)
11P: J1.6 R7.1 | length 1664.9
  Top Layer w30: R7.1@1712.55,2241.17 v1(1712.55,2288.17)
  Bottom Layer w30: J1.6@329.81,2578.64 329.81,2483.19 596,2217 1641.37,2217 v1(1712.55,2288.17)
12P: J1.5 R6.1 | length 2037.6
  Top Layer w30: R6.1@1801.45,2033.17 v1(1801.45,2080.17)
  Bottom Layer w30: J1.5@329.81,2716.64 269.43,2656.27 269.43,2426.57 522,2174 1707.63,2174 v1(1801.45,2080.17)
13P: J1.4 R5.1 | length 2072.2
  Top Layer w30: R5.1@1890.36,2241.17 v1(1890.36,2288.17)
  Bottom Layer w30: J1.4@309.81,2854.64 J1.4@319.81,2844.64 ; J1.4@329.81,2854.64 400,2784.45 400,2523 665.75,2257.25 1612.25,2257.25 1688,2333 1845.54,2333 v1(1890.36,2288.17)
14P: J1.3 R4.1 | length 2448.9
  Top Layer w30: R4.1@1979.27,2033.17 v1(1979.27,2080.17)
  Bottom Layer w30: J1.3@309.81,2992.64 J1.3@319.81,2982.64 ; J1.3@329.81,2992.64 386.34,2936.11 386.34,2916.11 462,2840.45 462,2551 717.87,2295.13 1558.81,2295.13 1640.69,2377 1872.42,2377 1979.27,2270.15 v1(1979.27,2080.17)
15P: J1.2 R3.1 | length 2423.5
  Top Layer w30: R3.1@2068.18,2241.17 v1(2068.18,2288.17)
  Bottom Layer w30: J1.2@309.81,3130.64 J1.2@319.81,3120.64 ; J1.2@329.81,3130.64 432,3028.45 432,2933 509,2856 509,2601 777,2333 1501,2333 1585.13,2417.13 1939.23,2417.13 v1(2068.18,2288.17)
16P: C28.2 D1.2 D4.2 D5.2 J1.1 Q2.1 Q2.2 Q2.3 R2.1 R31.1 TP2.1 | length 2148.6
  Top Layer w30: R2.1@2157.09,2033.17 v1(2157.09,2080.17)
  Bottom Layer w30: v1(848,3417) 975,3290 1086,3290 1229,3147 1419.81,3147 1493.91,3072.9 1543.09,3072.9 2066,2550 2066,2479.5 2177.55,2367.94 2177.55,2100.63 v1(2157.09,2080.17)
  other v1: 662,3383.37 705,3383 905,3417 847,3447 905,3448.5
BAT-: J3.6 NT1.2 R21.1 R25.1 R28.2 TP5.1 TP15.1 | length 225.2
  Top Layer w10: NT1.2@643,1093 NT1.2@643,1106
  Top Layer w20: NT1.2@644,1107 644,1151.1
  Top Layer w30: R28.2@921,1222.02 1003.98,1222.02 1029.5,1196.5 R25.1@1078.5,1196.5
BREG: Q1.1 U1.37 | length 496.3
  Top Layer w10: U1.37@1801.34,1111.73 1824.49,1111.73 1855,1081.22 1855,985 1920,920 1956.01,920 1995.2,880.81 Q1.1@1995.2,730.4
CD: D2.2 Q2.5 Q2.6 Q2.7 Q2.8 Q2.9 Q3.5 Q3.6 Q3.7 Q3.8 Q3.9
CHG: R37.1 TP19.1 U1.45 | length 950.4
  Top Layer w10: U1.45@1801.34,1269.21 1875.72,1269.21 1996.5,1390 2060,1390 2080,1410 2080,1493.37 2118.51,1531.87 2180.87,1531.87 2234,1585 2416.5,1585 TP19.1@2526.5,1695
DSG: D10.1 R41.1 TP23.1 U1.43 | length 1242.6
  Top Layer w10: U1.43@1801.34,1229.84 1889.84,1229.84 1934.57,1274.57 D10.1@1970.53,1274.57 ; R41.1@1970.53,1172.05 D10.1@1970.53,1274.57 ; TP23.1@2664.95,1695 2527.95,1558 2232.28,1558 2188.28,1514 2125.91,1514 2100,1488.09 2100,1345 2029.57,1274.57 D10.1@1970.53,1274.57
FUSE: R36.2 U1.38 | length 285.9
  Top Layer w10: U1.38@1801.34,1131.42 1849.02,1131.42 1879.84,1100.59 1879.84,995 1908.62,966.22 R36.2@1957.01,966.22
LD: R44.2 TP22.1 U1.41 | length 896.6
  Top Layer w10: U1.41@1801.34,1190.47 1846.77,1190.47 1900,1137.24 1900,1045.94 1934.95,1011 2137,1011 2198.68,1072.68 R44.2@2210,1072.68 2220.68,1072.68 2332,1184 2350.1,1184 TP22.1@2455,1288.9
NetC1_1: C1.1 C2.1 C5.1 R1.1 TP1.1 U1.47 | length 1133
  Top Layer w10: U1.47@1801.34,1308.58 1840.58,1308.58 1880,1348 1880,1375.12 C5.1@1959.88,1455 1959.88,1536.5 C2.1@1963.39,1540 1963.39,1614.7 1963.68,1615 1963.68,1623.68 2032.64,1692.64 TP1.1@2220,1692.64 ; TP1.1@2220,1695 2246,1721 R1.1@2246,2127
NetC3_1: C3.1 R2.2 U1.48 | length 764.5
  Top Layer w10: U1.48@1801.34,1328.27 1823.27,1328.27 1850,1355 1850,1427 1915,1492 C3.1@1915,1583.08 1915,1700 2134,1919 R2.2@2157.09,1919
NetC3_2: C3.2 C4.1 R3.2 U1.1 | length 875.2
  Top Layer w10: U1.1@1743.27,1386.34 1743.27,1409.27 1855,1521 C3.2@1855,1583.08 1855,1606 1867.67,1618.67 C4.1@1867.67,1632.08 1867.67,1696.67 2068.18,1897.18 R3.2@2068.18,2127
NetC4_2: C4.2 C6.1 R4.2 U1.2 | length 649.1
  Top Layer w10: U1.2@1723.58,1386.34 1723.58,1431.58 1820.33,1528.33 C6.1@1820.33,1583.08 1820.33,1610.06 1807.67,1622.73 C4.2@1807.67,1632.08 1807.67,1638.67 1830,1661 1830,1718 1979.27,1867.27 R4.2@1979.27,1919
NetC5_2: C5.2 TP3.1 U1.46 | length 782.4
  Top Layer w10: U1.46@1801.34,1288.9 1859.45,1288.9 1910,1339.45 1910,1368 1949.87,1407.87 1992.76,1407.87 C5.2@2039.88,1455 2039.88,1463.88 2056.93,1480.93 2056.93,1495.57 2111.11,1549.75 2164.75,1549.75 2226,1611 2301,1611 TP3.1@2385,1695
NetC6_2: C6.2 C7.1 R5.2 U1.3 | length 817.9
  Top Layer w10: U1.3@1703.9,1386.34 1703.9,1458.9 1760.33,1515.33 C6.2@1760.33,1583.08 1760.33,1608.04 1773,1620.7 C7.1@1773,1632.08 1773,1733.73 1890.36,1851.1 R5.2@1890.36,2127
NetC7_2: C7.2 C8.1 R6.2 U1.4 | length 591.7
  Top Layer w10: U1.4@1684.21,1386.34 1684.21,1534.21 1725.67,1575.67 C8.1@1725.67,1583.08 1725.67,1612.33 1713,1625 C7.2@1713,1632.08 1713,1757 1801.45,1845.45 R6.2@1801.45,1919
NetC8_2: C8.2 C9.1 R7.2 U1.5 | length 760.6
  Top Layer w10: U1.5@1664.53,1386.34 1664.53,1581.94 C8.2@1665.67,1583.08 1665.67,1612.67 1678.33,1625.33 C9.1@1678.33,1632.08 1678.33,1803 1712.55,1837.21 R7.2@1712.55,2127
NetC9_2: C9.2 C10.1 R8.2 U1.6 | length 545.8
  Top Layer w10: R8.2@1623.64,1919 1623.64,1637.39 C9.2@1618.33,1632.08 1618.33,1621.67 1631,1609 C10.1@1631,1583.08 1631,1538 1644.84,1524.16 U1.6@1644.84,1386.34
NetC10_2: C10.2 C11.1 R10.2 U1.7 | length 788.6
  Top Layer w10: R10.2@1534.73,2127 1534.73,1738.69 1583.67,1689.75 C11.1@1583.67,1632.08 1583.67,1621.67 1571,1609 C10.2@1571,1583.08 1571,1517 1625.16,1462.84 U1.7@1625.16,1386.34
